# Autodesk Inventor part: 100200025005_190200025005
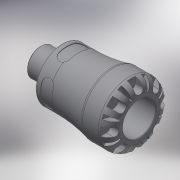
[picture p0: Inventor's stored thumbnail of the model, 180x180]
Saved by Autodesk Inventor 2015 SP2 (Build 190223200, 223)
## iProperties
Created: 2016-12
Part Number: 100200025005_190200025005
Material: Generic
Description: PLASSON MALE ADAPTOR 25X1/2" SERIES 1
Document SubType Name: Modeling
Designer: KIM
Mass: 447.839 g
Surface Area: 722.341 cm^2
Volume: 447.839 cm^3
Density: 1 g/cm^3
Appearance: Default
Author: KIM
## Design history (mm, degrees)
derived "1002.ipt"
feature "Solid1::1002.ipt"
tag "TaggingFeature1"
body "Solid1"
other parameters: "d0" = 75, "d1" = 20.16, "d2" = 25, "d3" = 31.25, "d4" = 47, "d6" = 48, "d8" = 39.95, "d13" = 6.3, "d14" = 6.3, "d15" = 0, "d17" = 360 deg, "d19" = 8 deg, "d20" = 0.5, "d21" = 0.5, "d22" = 8 deg, "d24" = 0, "d26" = 360 deg, "d32" = 0.925, "d33" = 4.7, "d34" = 20.955, "d35" = 5, "d38" = 16, "d39" = 0.62865, "d42" = 8.75, "d43" = 5.75, "d45" = 12.348, "d46" = 0, "d59" = 360 deg, "d61" = 7.4375, "d62" = 0.5, "d64" = 0, "d65" = 0.47, "d_" = 25, "E_" = 47, "H_" = 75, "l_" = 48, "R_" = 20.955, "l_2" = 16, "d9" = 7.875, "d11" = 47, "d12" = 31.25
